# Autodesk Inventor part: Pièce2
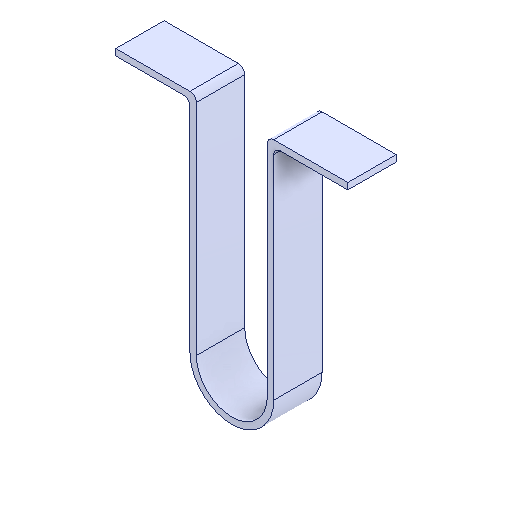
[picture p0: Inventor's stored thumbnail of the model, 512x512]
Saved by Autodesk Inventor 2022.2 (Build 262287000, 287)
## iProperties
Created: 2016-10
Part Number: Pièce2
Material: Generico
Document SubType Name: Modeling
Designer: 18907419
Density: 1 g/cm^3
Appearance: Default
Author: 18907419
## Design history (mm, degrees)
feature "Solido1"
node "Solido2"
